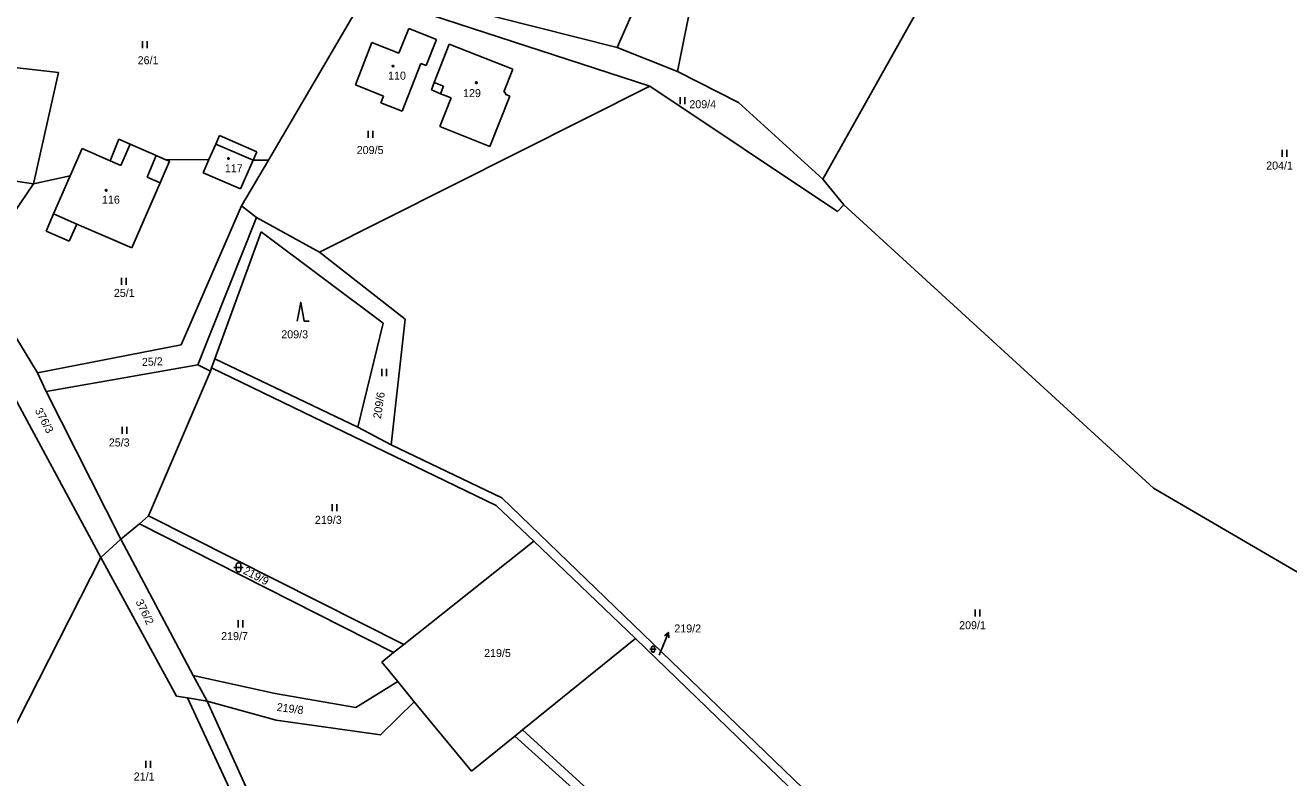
# Model space of a CAD drawing. Extents: x -811039 to -805820, y -1161436 to -1155864.
# Drawn here: x -806560.9 to -806292.6, y -1158370.8 to -1158211 of the extents above; entities that cross this region are included whole.
import ezdxf

# ---------------------------------------------------------------- set-up
doc = ezdxf.new("R2010")
doc.units = 0
for name, color, linetype in [('Default', 7, 'Continuous'), ('KN_HRANICE', 7, 'Continuous'), ('KN_KULTURY', 7, 'Continuous'), ('KN_PARCELY', 7, 'Continuous'), ('KN_SLUCKY', 7, 'Continuous')]:
    doc.layers.add(name, color=color, linetype=linetype)

# ---------------------------------------------------------------- blocks, each defined once
blk = doc.blocks.new('306')
at = {"layer": 'Default'}
for p, q in [((-0.5, 1.5), (-0.5, 0)), ((0.5, 0), (0.5, 1.5))]:
    blk.add_line(p, q, dxfattribs=at)
blk = doc.blocks.new('308')
at = {"layer": 'Default'}
blk.add_lwpolyline([(-0.75, 0), (0, 4), (0.75, 0), (1.75, 0)], dxfattribs=at)
blk = doc.blocks.new('316')
at = {"layer": 'Default'}
for points in [[(-1, 1), (0.27, 1), (1, 1)], [(-0.5, 1.5), (-0.4, 1.79), (-0.15, 1.97), (0.16, 1.97), (0.41, 1.79), (0.51, 1.5), (0.51, 0.5), (0.41, 0.21), (0.16, 0.03), (-0.15, 0.03), (-0.4, 0.21), (-0.5, 0.5), (-0.5, 1.5)]]:
    blk.add_lwpolyline(points, dxfattribs=at)
blk = doc.blocks.new('10292')
at = {"layer": 'Default'}
blk.add_line((0, 3), (0, 0), dxfattribs=at)
blk.add_lwpolyline([(-0.5, 2), (0, 3), (0.5, 2)], dxfattribs=at)
blk = doc.blocks.new('402')
at = {"layer": 'Default'}
blk.add_lwpolyline([(0.09, 0.15), (0.18, 0), (0.09, -0.15), (-0.09, -0.15), (-0.18, 0), (-0.09, 0.15), (0.09, 0.15)], dxfattribs=at)

msp = doc.modelspace()

# ---------------------------------------------------------------- linework, layer by layer
at = {"layer": 'KN_HRANICE'}
for p, q in [((-806391.51, -1158243.66), (-806342.79, -1158156.88)), ((-806419.28, -1158179.7), (-806435.17, -1158215.71)), ((-806422.34, -1158220.82), (-806416.11, -1158189.15)), ((-806435.17, -1158215.71), (-806496.95, -1158200.1)), ((-806509.26, -1158239.64), (-806488.49, -1158204.22)), ((-806488.49, -1158204.22), (-806428.22, -1158223.9)), ((-806481.53, -1158216.9), (-806479.45, -1158211.65)), ((-806479.45, -1158211.65), (-806473.58, -1158213.99)), ((-806473.58, -1158213.99), (-806475.76, -1158219.51)), ((-806490.79, -1158223.66), (-806487.28, -1158214.64)), ((-806487.28, -1158214.64), (-806481.53, -1158216.9)), ((-806474.07, -1158223.13), (-806470.85, -1158215)), ((-806470.85, -1158215), (-806457.33, -1158220.3)), ((-806435.17, -1158215.71), (-806422.34, -1158220.82)), ((-806569.88, -1158219.21), (-806553.85, -1158221)), ((-806476.88, -1158219.09), (-806480.85, -1158229.23)), ((-806475.76, -1158219.51), (-806476.88, -1158219.09)), ((-806553.85, -1158221), (-806559.13, -1158244.68)), ((-806457.33, -1158220.3), (-806459.26, -1158225.16)), ((-806409.4, -1158227.41), (-806422.34, -1158220.82)), ((-806498.43, -1158259.17), (-806428.22, -1158223.9)), ((-806484.78, -1158226.02), (-806490.79, -1158223.66)), ((-806474.59, -1158224.74), (-806474.07, -1158223.13)), ((-806472.69, -1158225.59), (-806474.59, -1158224.74)), ((-806428.22, -1158223.9), (-806388.39, -1158250.56)), ((-806485.35, -1158227.46), (-806484.78, -1158226.02)), ((-806480.85, -1158229.23), (-806485.35, -1158227.46)), ((-806472.83, -1158232.5), (-806470.41, -1158226.43)), ((-806470.41, -1158226.43), (-806472.69, -1158225.59)), ((-806457.98, -1158226.03), (-806462.22, -1158236.72)), ((-806459.26, -1158225.16), (-806458.82, -1158225.34)), ((-806458.82, -1158225.34), (-806458.95, -1158225.64)), ((-806458.95, -1158225.64), (-806457.98, -1158226.03)), ((-806391.51, -1158243.66), (-806409.4, -1158227.41)), ((-806462.22, -1158236.72), (-806472.83, -1158232.5)), ((-806542.85, -1158239.76), (-806541.01, -1158235.19)), ((-806541.01, -1158235.19), (-806538.61, -1158236.24)), ((-806520.45, -1158236.21), (-806519.67, -1158234.41)), ((-806519.67, -1158234.41), (-806511.73, -1158237.86)), ((-806551.36, -1158242.96), (-806548.84, -1158237.16)), ((-806548.84, -1158237.16), (-806542.85, -1158239.76)), ((-806538.61, -1158236.24), (-806533.07, -1158238.64)), ((-806521.88, -1158239.5), (-806520.45, -1158236.21)), ((-806512.52, -1158239.63), (-806511.73, -1158237.86)), ((-806531.01, -1158239.55), (-806533.07, -1158238.64)), ((-806530.26, -1158239.88), (-806532.22, -1158244.43)), ((-806531.01, -1158239.55), (-806521.88, -1158239.5)), ((-806530.26, -1158239.88), (-806531.01, -1158239.55)), ((-806523.1, -1158242.3), (-806521.88, -1158239.5)), ((-806512.52, -1158239.63), (-806515.19, -1158245.72)), ((-806514.95, -1158249.34), (-806509.26, -1158239.64)), ((-806512.52, -1158239.63), (-806509.26, -1158239.64)), ((-806559.13, -1158244.68), (-806566.82, -1158243.53)), ((-806559.13, -1158244.68), (-806551.36, -1158242.96)), ((-806554.88, -1158251.05), (-806551.36, -1158242.96)), ((-806515.19, -1158245.72), (-806523.1, -1158242.3)), ((-806387.05, -1158249.12), (-806391.51, -1158243.66)), ((-806564.83, -1158253.03), (-806559.13, -1158244.68)), ((-806532.22, -1158244.43), (-806538.26, -1158258.23)), ((-806388.39, -1158250.56), (-806387.05, -1158249.12)), ((-806321.3, -1158309.29), (-806387.05, -1158249.12)), ((-806556.46, -1158254.73), (-806554.88, -1158251.05)), ((-806527.79, -1158278.89), (-806514.95, -1158249.34)), ((-806524.28, -1158283.11), (-806511.82, -1158251.84)), ((-806511.82, -1158251.84), (-806514.95, -1158249.34)), ((-806511.82, -1158251.84), (-806498.43, -1158259.17)), ((-806549.95, -1158253.21), (-806551.57, -1158256.85)), ((-806538.26, -1158258.23), (-806549.95, -1158253.21)), ((-806551.57, -1158256.85), (-806556.46, -1158254.73)), ((-806510.79, -1158254.84), (-806520.62, -1158281.82)), ((-806510.79, -1158254.84), (-806484.85, -1158274.28)), ((-806480.2, -1158273.42), (-806498.43, -1158259.17)), ((-806567.55, -1158269.62), (-806558.32, -1158284.79)), ((-806544.86, -1158324.01), (-806572.8, -1158272.22)), ((-806484.85, -1158274.28), (-806490.25, -1158296.37)), ((-806483.21, -1158300.12), (-806480.2, -1158273.42)), ((-806558.32, -1158284.79), (-806527.79, -1158278.89)), ((-806556.49, -1158288.76), (-806524.28, -1158283.11)), ((-806524.28, -1158283.11), (-806521.59, -1158284.48)), ((-806521.33, -1158283.77), (-806521.59, -1158284.48)), ((-806520.62, -1158281.82), (-806521.33, -1158283.77)), ((-806521.33, -1158283.77), (-806460.92, -1158313)), ((-806490.25, -1158296.37), (-806520.62, -1158281.82)), ((-806558.32, -1158284.79), (-806556.49, -1158288.76)), ((-806521.59, -1158284.48), (-806534.73, -1158315.15)), ((-806556.49, -1158288.76), (-806540.62, -1158320.14)), ((-806490.25, -1158296.37), (-806483.21, -1158300.12)), ((-806483.21, -1158300.12), (-806459.69, -1158311.32)), ((-806321.3, -1158309.29), (-806282.26, -1158332.11)), ((-806460.92, -1158313), (-806452.92, -1158320.53)), ((-806459.69, -1158311.32), (-806386.78, -1158381.61)), ((-806536.6, -1158316.86), (-806534.73, -1158315.15)), ((-806480.47, -1158342.48), (-806534.73, -1158315.15)), ((-806540.62, -1158320.14), (-806536.6, -1158316.86)), ((-806482.66, -1158344.19), (-806536.6, -1158316.86)), ((-806544.86, -1158324.01), (-806540.62, -1158320.14)), ((-806540.62, -1158320.14), (-806525.27, -1158349.06)), ((-806480.47, -1158342.48), (-806452.92, -1158320.53)), ((-806452.92, -1158320.53), (-806431.28, -1158341.2)), ((-806568.24, -1158369.98), (-806544.86, -1158324.01)), ((-806544.86, -1158324.01), (-806528.76, -1158353.45)), ((-806482.66, -1158344.19), (-806480.47, -1158342.48)), ((-806455.31, -1158360.63), (-806431.28, -1158341.2)), ((-806431.28, -1158341.2), (-806387.94, -1158383.11)), ((-806485.18, -1158346.28), (-806482.66, -1158344.19)), ((-806481.76, -1158350.35), (-806485.18, -1158346.28)), ((-806522.26, -1158354.53), (-806525.27, -1158349.06)), ((-806525.27, -1158349.06), (-806507.84, -1158352.91)), ((-806490.71, -1158355.89), (-806481.76, -1158350.35)), ((-806478.28, -1158354.66), (-806481.76, -1158350.35)), ((-806528.76, -1158353.45), (-806526.45, -1158353.83)), ((-806512.77, -1158383.29), (-806526.45, -1158353.83)), ((-806526.45, -1158353.83), (-806522.26, -1158354.53)), ((-806507.84, -1158352.91), (-806490.71, -1158355.89)), ((-806522.26, -1158354.53), (-806507.59, -1158358.58)), ((-806522.26, -1158354.53), (-806511.25, -1158378.84)), ((-806485.47, -1158361.66), (-806478.28, -1158354.66)), ((-806466.14, -1158369.39), (-806478.28, -1158354.66)), ((-806507.59, -1158358.58), (-806485.47, -1158361.66)), ((-806466.14, -1158369.39), (-806456.91, -1158361.93)), ((-806456.91, -1158361.93), (-806455.31, -1158360.63)), ((-806387.39, -1158424.7), (-806456.91, -1158361.93)), ((-806386.82, -1158423), (-806455.31, -1158360.63))]:
    msp.add_line(p, q, dxfattribs=at)
at = {"layer": 'KN_PARCELY'}
msp.add_line((-806426.25, -1158344.75), (-806425.42, -1158342.72), dxfattribs=at)
at = {"layer": 'KN_SLUCKY'}
for p, q in [((-806474.07, -1158223.13), (-806472.05, -1158223.95)), ((-806472.05, -1158223.95), (-806472.69, -1158225.59)), ((-806540.57, -1158240.75), (-806538.61, -1158236.24)), ((-806520.45, -1158236.21), (-806512.52, -1158239.63)), ((-806542.85, -1158239.76), (-806540.57, -1158240.75)), ((-806533.07, -1158238.64), (-806535.02, -1158243.22)), ((-806535.02, -1158243.22), (-806532.22, -1158244.43)), ((-806549.95, -1158253.21), (-806554.88, -1158251.05))]:
    msp.add_line(p, q, dxfattribs=at)

# ---------------------------------------------------------------- block references
at = {"layer": 'KN_KULTURY'}
for name, p in [('306', (-806535.52, -1158215.84)), ('402', (-806482.8, -1158219.66)), ('402', (-806465.08, -1158223.19)), ('306', (-806421.31, -1158227.76)), ('306', (-806487.58, -1158234.9)), ('306', (-806293.46, -1158238.93)), ('402', (-806517.73, -1158239.28)), ('402', (-806543.73, -1158246.05)), ('306', (-806539.94, -1158266.15)), ('308', (-806502.38, -1158273.84)), ('306', (-806484.7, -1158285.48)), ('306', (-806539.84, -1158297.74)), ('306', (-806495.25, -1158314.17)), ('316', (-806515.59, -1158327.11)), ('306', (-806358.67, -1158336.54)), ('306', (-806515.16, -1158338.86)), ('306', (-806534.77, -1158368.68))]:
    msp.add_blockref(name, p, dxfattribs=at)
at = {"layer": 'KN_KULTURY', "xscale": 0.67, "yscale": 0.67}
msp.add_blockref('316', (-806427.58, -1158344.17), dxfattribs=at)
at = {"layer": 'KN_PARCELY', "rotation": -22.184083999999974}
msp.add_blockref('10292', (-806425.42, -1158342.72), dxfattribs=at)

# ---------------------------------------------------------------- texts
at = {"layer": 'KN_PARCELY'}
for s, height, p in [('26/1', 1.7, (-806537.03, -1158219.27)), ('110', 1.7, (-806483.84, -1158222.54)), ('129', 1.7, (-806467.92, -1158226.25)), ('209/4', 1.7, (-806419.86, -1158228.61)), ('209/5', 1.7, (-806490.5, -1158238.34)), ('117', 1.7, (-806518.51, -1158242.2)), ('204/1', 1.7, (-806297.35, -1158241.63)), ('116', 1.7, (-806544.6, -1158248.88)), ('25/1', 1.7, (-806542.08, -1158268.68)), ('209/3', 1.7, (-806506.52, -1158277.47)), ('25/3', 1.7, (-806543.16, -1158300.44)), ('219/3', 1.7, (-806499.38, -1158316.87)), ('209/1', 1.7, (-806362.56, -1158339.24)), ('219/7', 1.7, (-806519.29, -1158341.56)), ('219/2', 1.7, (-806423.05, -1158339.94)), ('219/5', 1.7, (-806463.45, -1158345.15)), ('219/2', 0.1, (-806426.49, -1158344.75)), ('21/1', 1.7, (-806537.85, -1158371.38))]:
    msp.add_text(s, height=height, dxfattribs=at).set_placement(p)
for s, rotation, p in [('25/2', 2.349, (-806536.09, -1158283.36)), ('209/6', 81.36, (-806485.37, -1158294.64)), ('376/3', 297.652, (-806558.92, -1158292.78)), ('219/9', 332.43, (-806514.77, -1158327.35)), ('376/2', 295.761, (-806537.52, -1158333.39)), ('219/8', 352.656, (-806507.57, -1158356.58))]:
    msp.add_text(s, height=1.7, rotation=rotation, dxfattribs=at).set_placement(p)

doc.saveas('drawing.dxf')
